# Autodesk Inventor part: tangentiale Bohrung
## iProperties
Created: 2005-01
Part Number: tangentiale Bohrung
Document SubType Name: Modeling
Designer: Wolff
Manufacturer: Standard
Standards Organization: Custom
Author: Wolff
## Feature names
1. Extrusion1
2. Bohrung1 [Hole]
